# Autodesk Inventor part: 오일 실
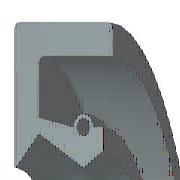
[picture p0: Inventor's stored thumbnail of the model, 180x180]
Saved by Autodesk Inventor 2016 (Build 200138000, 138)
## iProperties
IsCustomPart: 0
Created: 2014-10
Part Number: 오일 실
Material: 고무
Description: 오일-실
Document SubType Name: Modeling
Standard: KS B 2804
Designer: KYOUNG IL JANG
Standards Organization: KS
Language: ko-KR
Size Designation: D - 17 32 8
Categories: <MemberInstance><Categories><Category DisplayName="샤프트 부품" InternalName="7f7aeb1f-a693-4053-b835-cee3144e0d98" Mnemonic="SHFT"><Category DisplayName="실링" Intern
Density: 0.93 g/cm^3
Mass: 2.28027 g
Surface Area: 32.1224 cm^2
Volume: 2.45191 cm^3
Appearance: 고무 - 검은색 - 버전 1.1
Author: SeoGD™ [www.esajin.kr]
Revision Number: 1
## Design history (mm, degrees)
revolve "본체" stored, may be unused: angle "d17" = 90 deg
revolve "스프링1" stored, may be unused: angle "d18" = 90 deg
body "Solid1"
sketch "스케치1"
  geometry: L1 (0, 16)-(8, 16); L2 (8, 14.25)-(1.75, 14.25); L3 (1.75, 10.25)-(4.9, 8.5); L4 (4.9, 8.5)-(0, 8.5); L5 (0, 0)-(9.586, 0) reference; L6 (4.9, 8.5)-(6.3, 9.375); L7 (0, 18)-(0, -3) reference; L8 (-1.941, 0)-(11.507, 0) reference; L9 (4.2, 10.6)-(1.75, 11.21); L10 (1.75, 11.21)-(1.75, 14.25); L11 (0, 16)-(0, 8.588); L12 (4.9, 8.5)-(0, 8.5); L13 (1.75, 10.25)-(0.152, 8.528); L14 (8, 16)-(8, 14.25); L15 (5.6, 10.6)-(6.3, 10.6); L16 (6.3, 10.6)-(6.3, 9.375); C1 r 0.455 at (4.9, 10.6); A1 r 0.7 centre (4.9, 10.6) between (5.6, 10.6) and (4.2, 10.6); A2 r 0.088 centre (0.088, 8.588) between (0, 8.588) and (0.152, 8.528); 1 further point
  constraints: 28 end point, 5 horizontal alignment, 5 point on line, 4 point on circle, 4 vertical alignment, 3 centre point, 3 tangent, 2 collinear, 2 horizontal, 2 perpendicular, 1 coincident, 1 parallel
  dimensions: "d0" = 32 diameter of L1 L5 (= SD2); "d1" = 1.75 distance of L1.end L2.start (= SD); "d2" = 0.91 diameter of C1 (= SPDI); "d3" = 1.4 diameter of A1 (= SPDA); "d4" = 17 diameter of L3.end L5 (= NND); "d5" = 20.5 diameter of L3.start L5 (= TKDM); "d7" = 22.42 diameter of L9.end L5 (= TKDM + 0.24 x SWDT); "d8" = 1.75 distance between parallel lines of L11 L10 (= SD); "d9" = 4.9 distance from line of L11 C1.centre (= SPDST); "d10" = 21.2 diameter of C1.centre L5 (= HLDM); "d11" = 0.0875 radius of A2 (= 0.25 x LAB); "d12" = 6.3 distance between parallel lines of L11 L16 (= SDI); "d13" = 18.75 diameter of L6.end L5 (= ABDM); "d14" = 8 distance from line of L11 L1.end (= SWDT)
fillet "모깎기1" dims "d6" = 0.3 (= RR)
other parameters: "SD2" = 32 [user parameter; used in 1 equation term], "SWDT" = 8 [user parameter; used in 2 equation terms], "RR" = 0.3 [user parameter; used in 1 equation term], "SD" = 1.75 [user parameter; used in 2 equation terms], "NND" = 17 [user parameter; used in 1 equation term], "SPDA" = 1.4 [user parameter; used in 1 equation term], "SPDI" = 0.91 [user parameter; used in 1 equation term], "TKDM" = 20.5 [user parameter; used in 2 equation terms], "HLDM" = 21.2 [user parameter; used in 1 equation term], "ABDM" = 18.75 [user parameter; used in 1 equation term], "SDI" = 6.3 [user parameter; used in 1 equation term], "SPDST" = 4.9 [user parameter; used in 1 equation term], "LAB" = 0.35 [user parameter; used in 1 equation term], "d15" = 0, "d16" = 0, "d19" = 0
